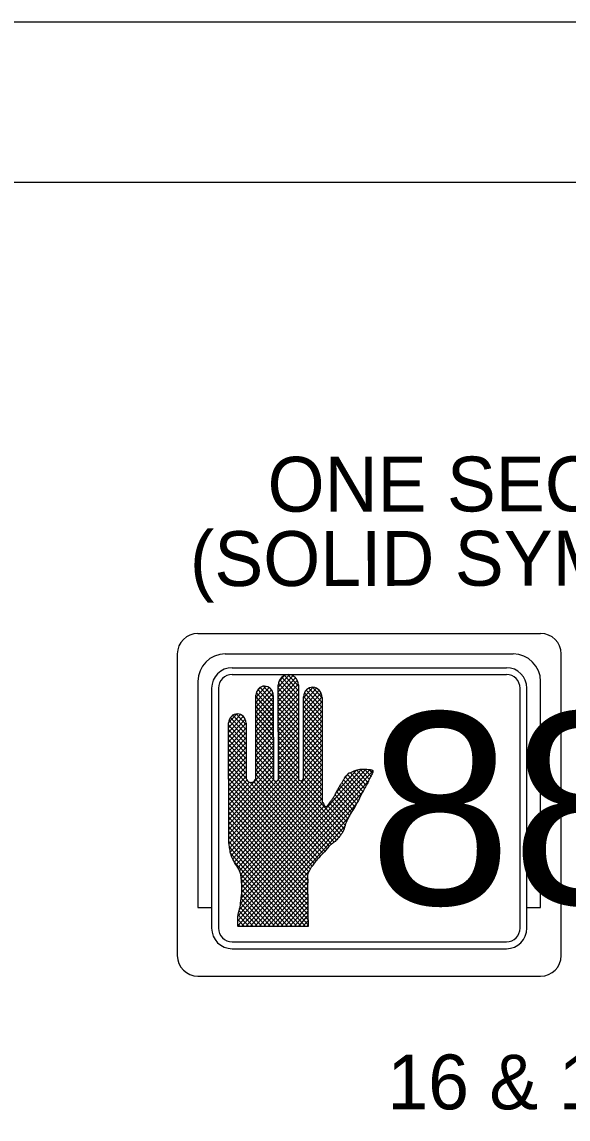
# Model space of a CAD drawing. Extents: x 1710114 to 1711114, y 557211 to 557851.
# Drawn here: x 1710492.9 to 1710532.7, y 557771.1 to 557851.1 of the extents above; entities that cross this region are included whole.
import ezdxf

# ---------------------------------------------------------------- set-up
doc = ezdxf.new("R2010")
doc.units = 0
for name, color, linetype in [('E_Existing ROW', 7, 'Continuous'), ('R_Alt Surface', 7, 'Continuous'), ('R_Alt Surface Annot', 7, 'Continuous'), ('R_Dimension', 7, 'Continuous')]:
    doc.layers.add(name, color=color, linetype=linetype)

msp = doc.modelspace()

# ---------------------------------------------------------------- linework, layer by layer
at = {"layer": 'E_Existing ROW'}
for p, q in [((1710505.726, 557806.546), (1710530.726, 557806.546)), ((1710504.226, 557805.046), (1710504.226, 557783.046)), ((1710507.726, 557805.046), (1710528.726, 557805.046)), ((1710532.226, 557783.046), (1710532.226, 557805.046)), ((1710508.226, 557804.046), (1710528.226, 557804.046)), ((1710505.726, 557803.046), (1710505.726, 557786.546)), ((1710508.226, 557803.546), (1710528.226, 557803.546)), ((1710511.59, 557802.63), (1710512.412, 557803.543)), ((1710511.59, 557802.277), (1710512.655, 557803.46)), ((1710511.591, 557801.924), (1710512.84, 557803.312)), ((1710511.591, 557801.571), (1710512.974, 557803.107)), ((1710511.592, 557801.218), (1710513.049, 557802.837)), ((1710511.605, 557802.905), (1710513.055, 557801.294)), ((1710511.644, 557803.043), (1710512.045, 557803.489)), ((1710511.696, 557803.158), (1710513.055, 557801.648)), ((1710511.841, 557803.35), (1710513.054, 557802.002)), ((1710512.037, 557803.486), (1710513.054, 557802.356)), ((1710512.298, 557803.549), (1710513.053, 557802.71)), ((1710512.765, 557803.384), (1710512.906, 557803.227)), ((1710513.053, 557802.792), (1710513.061, 557796.014)), ((1710530.726, 557786.546), (1710530.726, 557803.046)), ((1710506.726, 557802.546), (1710506.726, 557785.046)), ((1710507.226, 557802.546), (1710507.226, 557785.046)), ((1710509.952, 557801.871), (1710510.689, 557802.69)), ((1710509.952, 557801.518), (1710510.921, 557802.594)), ((1710509.958, 557796.073), (1710509.952, 557802.038)), ((1710509.953, 557801.164), (1710511.09, 557802.428)), ((1710509.953, 557800.811), (1710511.198, 557802.195)), ((1710509.987, 557802.228), (1710511.226, 557800.851)), ((1710510.009, 557802.288), (1710510.32, 557802.633)), ((1710510.104, 557802.452), (1710511.226, 557801.205)), ((1710510.279, 557802.61), (1710511.225, 557801.559)), ((1710510.521, 557802.695), (1710511.225, 557801.913)), ((1710510.946, 557802.576), (1710511.115, 557802.388)), ((1710511.224, 557802.024), (1710511.231, 557795.978)), ((1710511.597, 557795.946), (1710511.59, 557802.773)), ((1710511.59, 557802.568), (1710513.055, 557800.94)), ((1710511.59, 557802.214), (1710513.056, 557800.586)), ((1710511.592, 557800.865), (1710513.054, 557802.489)), ((1710511.592, 557800.512), (1710513.054, 557802.136)), ((1710513.42, 557801.835), (1710514.126, 557802.619)), ((1710513.421, 557801.482), (1710514.383, 557802.551)), ((1710513.421, 557801.129), (1710514.572, 557802.408)), ((1710513.421, 557800.776), (1710514.708, 557802.205)), ((1710513.497, 557802.217), (1710514.782, 557800.789)), ((1710513.635, 557802.417), (1710514.782, 557801.143)), ((1710513.827, 557802.557), (1710514.782, 557801.497)), ((1710514.089, 557802.62), (1710514.781, 557801.851)), ((1710529.226, 557785.046), (1710529.226, 557802.546)), ((1710529.726, 557785.046), (1710529.726, 557802.546)), ((1710509.952, 557801.914), (1710511.227, 557800.497)), ((1710509.952, 557801.56), (1710511.227, 557800.143)), ((1710509.953, 557800.458), (1710511.225, 557801.871)), ((1710509.953, 557801.206), (1710511.227, 557799.789)), ((1710509.954, 557800.105), (1710511.225, 557801.518)), ((1710511.591, 557801.86), (1710513.056, 557800.232)), ((1710511.591, 557801.506), (1710513.057, 557799.878)), ((1710511.593, 557800.158), (1710513.054, 557801.782)), ((1710511.593, 557799.805), (1710513.055, 557801.429)), ((1710513.427, 557795.981), (1710513.42, 557801.929)), ((1710513.421, 557801.595), (1710514.783, 557800.081)), ((1710513.421, 557801.241), (1710514.783, 557799.727)), ((1710513.422, 557801.947), (1710514.783, 557800.435)), ((1710513.422, 557800.423), (1710514.779, 557801.931)), ((1710513.422, 557800.07), (1710514.782, 557801.58)), ((1710513.423, 557799.717), (1710514.782, 557801.227)), ((1710514.781, 557801.882), (1710514.79, 557794.225)), ((1710507.964, 557800.015), (1710508.559, 557800.677)), ((1710507.964, 557799.662), (1710508.834, 557800.629)), ((1710507.964, 557799.309), (1710509.03, 557800.493)), ((1710508.11, 557800.424), (1710509.238, 557799.171)), ((1710508.284, 557800.585), (1710509.237, 557799.525)), ((1710508.523, 557800.673), (1710509.237, 557799.879)), ((1710508.926, 557800.579), (1710509.148, 557800.332)), ((1710509.953, 557800.852), (1710511.228, 557799.435)), ((1710509.953, 557800.498), (1710511.228, 557799.081)), ((1710509.954, 557799.752), (1710511.226, 557801.165)), ((1710509.955, 557799.399), (1710511.226, 557800.812)), ((1710509.955, 557799.046), (1710511.227, 557800.459)), ((1710511.592, 557801.152), (1710513.057, 557799.524)), ((1710511.592, 557800.798), (1710513.057, 557799.17)), ((1710511.592, 557800.444), (1710513.058, 557798.816)), ((1710511.594, 557799.452), (1710513.055, 557801.076)), ((1710511.594, 557799.099), (1710513.056, 557800.723)), ((1710513.421, 557800.887), (1710514.784, 557799.373)), ((1710513.422, 557800.533), (1710514.784, 557799.019)), ((1710513.423, 557799.364), (1710514.782, 557800.874)), ((1710513.423, 557799.011), (1710514.783, 557800.521)), ((1710507.973, 557791.775), (1710507.963, 557800.018)), ((1710507.964, 557799.88), (1710509.239, 557798.463)), ((1710507.965, 557798.956), (1710509.168, 557800.292)), ((1710507.965, 557798.603), (1710509.236, 557800.015)), ((1710507.966, 557798.249), (1710509.237, 557799.662)), ((1710507.996, 557800.198), (1710509.238, 557798.817)), ((1710509.237, 557800.003), (1710509.241, 557796.072)), ((1710509.954, 557800.144), (1710511.229, 557798.727)), ((1710509.954, 557799.79), (1710511.229, 557798.373)), ((1710509.955, 557798.693), (1710511.227, 557800.106)), ((1710509.956, 557798.34), (1710511.227, 557799.752)), ((1710511.593, 557800.09), (1710513.058, 557798.462)), ((1710511.593, 557799.736), (1710513.058, 557798.108)), ((1710511.594, 557798.746), (1710513.056, 557800.37)), ((1710511.595, 557798.393), (1710513.056, 557800.017)), ((1710511.595, 557798.04), (1710513.057, 557799.664)), ((1710513.422, 557800.179), (1710514.785, 557798.665)), ((1710513.423, 557799.825), (1710514.785, 557798.311)), ((1710513.424, 557798.657), (1710514.783, 557800.168)), ((1710513.424, 557798.304), (1710514.783, 557799.814)), ((1710507.964, 557799.526), (1710509.239, 557798.109)), ((1710507.965, 557799.172), (1710509.239, 557797.755)), ((1710507.965, 557798.818), (1710509.24, 557797.401)), ((1710507.966, 557797.896), (1710509.238, 557799.309)), ((1710507.966, 557797.543), (1710509.238, 557798.956)), ((1710509.955, 557799.436), (1710511.229, 557798.019)), ((1710509.955, 557799.082), (1710511.23, 557797.665)), ((1710509.956, 557797.986), (1710511.228, 557799.399)), ((1710509.957, 557797.633), (1710511.228, 557799.046)), ((1710511.594, 557799.382), (1710513.059, 557797.754)), ((1710511.594, 557799.028), (1710513.059, 557797.4)), ((1710511.596, 557797.687), (1710513.057, 557799.311)), ((1710511.596, 557797.334), (1710513.058, 557798.958)), ((1710513.423, 557799.471), (1710514.785, 557797.957)), ((1710513.423, 557799.117), (1710514.786, 557797.603)), ((1710513.425, 557797.951), (1710514.784, 557799.461)), ((1710513.425, 557797.598), (1710514.784, 557799.108)), ((1710507.965, 557798.464), (1710509.24, 557797.047)), ((1710507.966, 557798.11), (1710509.241, 557796.693)), ((1710507.967, 557797.19), (1710509.238, 557798.603)), ((1710507.967, 557796.837), (1710509.239, 557798.25)), ((1710509.955, 557798.728), (1710511.23, 557797.311)), ((1710509.956, 557798.374), (1710511.231, 557796.957)), ((1710509.956, 557798.02), (1710511.231, 557796.603)), ((1710509.957, 557797.28), (1710511.229, 557798.693)), ((1710509.957, 557796.927), (1710511.229, 557798.34)), ((1710509.958, 557796.574), (1710511.229, 557797.987)), ((1710511.594, 557798.674), (1710513.06, 557797.046)), ((1710511.595, 557798.32), (1710513.06, 557796.692)), ((1710511.596, 557796.98), (1710513.058, 557798.604)), ((1710511.597, 557796.627), (1710513.058, 557798.251)), ((1710513.424, 557798.763), (1710514.786, 557797.249)), ((1710513.424, 557798.409), (1710514.786, 557796.895)), ((1710513.425, 557797.245), (1710514.784, 557798.755)), ((1710513.425, 557798.055), (1710514.787, 557796.541)), ((1710513.426, 557796.892), (1710514.785, 557798.402)), ((1710513.426, 557796.539), (1710514.785, 557798.049)), ((1710507.966, 557797.756), (1710509.241, 557796.339)), ((1710507.966, 557797.402), (1710509.253, 557795.973)), ((1710507.967, 557796.484), (1710509.239, 557797.897)), ((1710507.968, 557796.131), (1710509.24, 557797.544)), ((1710507.968, 557795.778), (1710509.24, 557797.191)), ((1710507.97, 557793.659), (1710511.23, 557797.281)), ((1710507.985, 557791.553), (1710513.06, 557797.192)), ((1710508.265, 557790.097), (1710514.786, 557797.342)), ((1710509.957, 557797.666), (1710511.231, 557796.249)), ((1710509.957, 557797.312), (1710511.247, 557795.878)), ((1710509.958, 557796.221), (1710511.23, 557797.634)), ((1710511.594, 557795.917), (1710513.059, 557797.545)), ((1710511.595, 557797.966), (1710513.06, 557796.338)), ((1710511.596, 557797.612), (1710513.055, 557795.99)), ((1710511.596, 557797.258), (1710516.29, 557792.043)), ((1710511.597, 557796.274), (1710513.059, 557797.898)), ((1710513.425, 557797.701), (1710514.787, 557796.187)), ((1710513.425, 557797.347), (1710514.787, 557795.834)), ((1710513.427, 557796.186), (1710514.785, 557797.695)), ((1710507.967, 557797.048), (1710514.344, 557789.962)), ((1710507.967, 557796.694), (1710514.197, 557789.772)), ((1710507.969, 557795.424), (1710509.24, 557796.838)), ((1710507.969, 557795.071), (1710509.241, 557796.484)), ((1710507.971, 557793.306), (1710511.231, 557796.928)), ((1710507.971, 557792.953), (1710511.231, 557796.574)), ((1710507.996, 557791.212), (1710513.06, 557796.839)), ((1710508.045, 557790.913), (1710513.06, 557796.486)), ((1710508.389, 557789.881), (1710514.786, 557796.989)), ((1710508.514, 557789.666), (1710514.787, 557796.636)), ((1710508.648, 557785.573), (1710518.495, 557796.513)), ((1710508.659, 557785.938), (1710518.264, 557796.611)), ((1710508.764, 557786.408), (1710517.975, 557796.643)), ((1710508.834, 557786.84), (1710517.657, 557796.643)), ((1710509.957, 557796.958), (1710515.304, 557791.017)), ((1710509.958, 557796.604), (1710515.147, 557790.838)), ((1710511.596, 557796.904), (1710516.15, 557791.844)), ((1710511.597, 557796.55), (1710516, 557791.657)), ((1710513.426, 557796.993), (1710514.788, 557795.48)), ((1710513.426, 557796.639), (1710514.788, 557795.126)), ((1710515.828, 557794.965), (1710517.283, 557796.582)), ((1710516.832, 557796.39), (1710517.874, 557795.233)), ((1710517.057, 557796.494), (1710518.002, 557795.444)), ((1710517.292, 557796.586), (1710518.124, 557795.662)), ((1710517.559, 557796.643), (1710518.225, 557795.903)), ((1710517.877, 557796.643), (1710518.338, 557796.131)), ((1710518.219, 557796.617), (1710518.449, 557796.361)), ((1710507.968, 557796.34), (1710514.063, 557789.568)), ((1710507.968, 557795.986), (1710513.919, 557789.374)), ((1710507.968, 557795.632), (1710513.807, 557789.144)), ((1710507.969, 557794.718), (1710509.241, 557796.131)), ((1710507.97, 557794.365), (1710509.304, 557795.848)), ((1710507.97, 557794.012), (1710509.485, 557795.696)), ((1710507.972, 557792.599), (1710511.231, 557796.221)), ((1710507.972, 557792.246), (1710511.245, 557795.883)), ((1710507.972, 557791.893), (1710511.455, 557795.763)), ((1710508.094, 557790.614), (1710513.061, 557796.133)), ((1710508.158, 557790.332), (1710513.119, 557795.843)), ((1710508.638, 557789.45), (1710514.787, 557796.283)), ((1710508.649, 557785.22), (1710518.188, 557795.819)), ((1710508.759, 557789.231), (1710514.787, 557795.93)), ((1710508.853, 557788.982), (1710514.788, 557795.577)), ((1710509.509, 557795.688), (1710514.504, 557790.138)), ((1710509.787, 557795.733), (1710514.666, 557790.312)), ((1710509.933, 557795.925), (1710514.829, 557790.484)), ((1710509.958, 557796.25), (1710514.991, 557790.658)), ((1710511.339, 557795.776), (1710515.475, 557791.18)), ((1710511.577, 557795.866), (1710515.663, 557791.325)), ((1710511.597, 557796.196), (1710515.844, 557791.478)), ((1710513.234, 557795.792), (1710516.384, 557792.292)), ((1710513.42, 557795.939), (1710514.789, 557794.418)), ((1710513.427, 557796.285), (1710514.788, 557794.772)), ((1710516.232, 557795.643), (1710517.41, 557794.334)), ((1710516.353, 557795.862), (1710517.527, 557794.557)), ((1710516.429, 557795.986), (1710516.771, 557796.366)), ((1710516.484, 557796.069), (1710517.639, 557794.786)), ((1710516.635, 557796.255), (1710517.751, 557795.015)), ((1710507.969, 557795.278), (1710513.723, 557788.884)), ((1710507.969, 557794.924), (1710513.734, 557788.518)), ((1710508.888, 557788.668), (1710514.788, 557795.223)), ((1710508.914, 557785.161), (1710517.712, 557794.937)), ((1710508.919, 557788.349), (1710514.788, 557794.87)), ((1710515.743, 557794.772), (1710516.908, 557793.477)), ((1710515.848, 557795.008), (1710517.039, 557793.685)), ((1710515.969, 557795.228), (1710517.169, 557793.895)), ((1710516.093, 557795.444), (1710517.291, 557794.113)), ((1710507.969, 557794.57), (1710513.72, 557788.18)), ((1710507.97, 557794.216), (1710513.721, 557787.826)), ((1710508.879, 557787.244), (1710514.951, 557793.991)), ((1710508.935, 557787.66), (1710514.835, 557794.214)), ((1710508.938, 557788.016), (1710514.789, 557794.517)), ((1710509.232, 557785.161), (1710517.294, 557794.118)), ((1710515.173, 557793.99), (1710516.465, 557792.555)), ((1710515.322, 557794.179), (1710516.56, 557792.803)), ((1710515.47, 557794.368), (1710516.668, 557793.037)), ((1710515.604, 557794.573), (1710516.786, 557793.259)), ((1710507.97, 557793.862), (1710513.737, 557787.455)), ((1710507.971, 557793.508), (1710513.739, 557787.099)), ((1710507.971, 557793.154), (1710513.739, 557786.745)), ((1710507.971, 557792.8), (1710513.74, 557786.391)), ((1710507.972, 557792.446), (1710513.742, 557786.035)), ((1710509.551, 557785.162), (1710516.711, 557793.118)), ((1710509.87, 557785.162), (1710516.428, 557792.45)), ((1710507.972, 557792.092), (1710513.756, 557785.666)), ((1710507.975, 557791.736), (1710513.776, 557785.29)), ((1710507.987, 557791.369), (1710513.568, 557785.167)), ((1710508.037, 557790.96), (1710513.25, 557785.167)), ((1710508.109, 557790.526), (1710512.933, 557785.166)), ((1710508.42, 557789.827), (1710512.615, 557785.166)), ((1710510.188, 557785.163), (1710513.861, 557789.244)), ((1710508.851, 557788.995), (1710512.297, 557785.166)), ((1710508.897, 557788.59), (1710511.979, 557785.165)), ((1710510.507, 557785.163), (1710513.73, 557788.745)), ((1710510.825, 557785.164), (1710513.728, 557788.389)), ((1710508.929, 557788.201), (1710511.661, 557785.165)), ((1710508.941, 557787.834), (1710511.344, 557785.164)), ((1710511.144, 557785.164), (1710513.719, 557788.025)), ((1710511.462, 557785.164), (1710513.727, 557787.68)), ((1710508.839, 557786.887), (1710510.39, 557785.163)), ((1710508.873, 557787.202), (1710510.708, 557785.163)), ((1710508.92, 557787.504), (1710511.026, 557785.164)), ((1710511.781, 557785.165), (1710513.738, 557787.34)), ((1710512.1, 557785.165), (1710513.739, 557786.987)), ((1710505.726, 557786.546), (1710506.726, 557786.546)), ((1710508.664, 557786.02), (1710509.437, 557785.162)), ((1710508.729, 557786.302), (1710509.755, 557785.162)), ((1710508.803, 557786.573), (1710510.072, 557785.162)), ((1710512.418, 557785.166), (1710513.739, 557786.633)), ((1710512.737, 557785.166), (1710513.74, 557786.28)), ((1710529.726, 557786.546), (1710530.726, 557786.546)), ((1710508.649, 557785.33), (1710508.801, 557785.161)), ((1710508.674, 557785.161), (1710508.649, 557785.192)), ((1710508.65, 557785.683), (1710509.119, 557785.161)), ((1710513.055, 557785.167), (1710513.745, 557785.933)), ((1710513.374, 557785.167), (1710513.759, 557785.595)), ((1710513.693, 557785.168), (1710513.776, 557785.26)), ((1710513.753, 557785.168), (1710508.674, 557785.161)), ((1710513.777, 557785.162), (1710513.753, 557785.168)), ((1710508.226, 557784.046), (1710528.226, 557784.046)), ((1710508.226, 557783.546), (1710528.226, 557783.546)), ((1710505.726, 557781.546), (1710530.726, 557781.546))]:
    msp.add_line(p, q, dxfattribs=at)
for centre, radius, start, end in [((1710505.726, 557805.046), 1.5, 90, 180), ((1710530.726, 557805.046), 1.5, 0, 90), ((1710507.726, 557803.046), 2, 90, 180), ((1710528.726, 557803.046), 2, 0, 90), ((1710508.226, 557802.546), 1.5, 90, 180), ((1710528.226, 557802.546), 1.5, 0, 90), ((1710508.226, 557802.546), 1, 90, 180), ((1710528.226, 557802.546), 1, 0, 90), ((1710508.226, 557785.046), 1.5, 180, 270), ((1710508.226, 557785.046), 1, 180, 270), ((1710528.226, 557785.046), 1.5, 270, 0), ((1710528.226, 557785.046), 1, 270, 0), ((1710505.726, 557783.046), 1.5, 180, 270), ((1710530.726, 557783.046), 1.5, 270, 0)]:
    msp.add_arc(centre, radius, start, end, dxfattribs=at)
for centre, major_axis, start_param, end_param in [((1710512.322, 557802.735), (0, -0.814), 1.640121, 4.665593), ((1710510.588, 557801.99), (0, -0.709), 1.618611, 4.644084), ((1710514.099, 557801.862), (0, -0.758), 1.597842, 4.623315), ((1710508.6, 557799.97), (0, -0.709), 1.618611, 4.644084), ((1710509.6, 557796.073), (0, -0.398), 4.713646, 7.855239), ((1710511.415, 557795.962), (0, -0.204), 4.633755, 7.775348), ((1710513.241, 557795.999), (0, -0.207), 4.624552, 7.766145)]:
    msp.add_ellipse(centre, major_axis=major_axis, ratio=0.9, start_param=start_param, end_param=end_param, dxfattribs=at)
for points in [[(1710514.789, 557794.226), (1710514.84, 557794.212), (1710514.91, 557794.057), (1710514.998, 557793.938), (1710515.05, 557793.919), (1710515.138, 557793.939), (1710515.192, 557794.019), (1710515.35, 557794.213), (1710515.473, 557794.371), (1710515.543, 557794.487), (1710515.613, 557794.585), (1710515.736, 557794.761), (1710515.806, 557794.918), (1710515.911, 557795.133), (1710515.982, 557795.251), (1710516.105, 557795.465), (1710516.245, 557795.662), (1710516.351, 557795.857), (1710516.473, 557796.052), (1710516.58, 557796.19), (1710516.736, 557796.347), (1710516.929, 557796.426), (1710517.036, 557796.485), (1710517.194, 557796.542), (1710517.334, 557796.603), (1710517.547, 557796.643), (1710517.722, 557796.643), (1710517.951, 557796.643), (1710518.162, 557796.624), (1710518.408, 557796.585), (1710518.478, 557796.544), (1710518.494, 557796.487), (1710518.391, 557796.233), (1710518.32, 557796.095), (1710518.251, 557795.957), (1710518.18, 557795.802), (1710518.144, 557795.704), (1710518.004, 557795.449), (1710517.795, 557795.097), (1710517.513, 557794.53), (1710517.162, 557793.882), (1710516.882, 557793.432), (1710516.723, 557793.139), (1710516.583, 557792.864), (1710516.501, 557792.646), (1710516.458, 557792.535), (1710516.301, 557792.063), (1710516.056, 557791.73), (1710515.862, 557791.496), (1710515.582, 557791.259), (1710515.405, 557791.122), (1710514.949, 557790.612), (1710514.545, 557790.183), (1710514.282, 557789.888), (1710514.053, 557789.554), (1710513.939, 557789.409), (1710513.843, 557789.204), (1710513.737, 557789.007), (1710513.737, 557788.577), (1710513.72, 557788.191), (1710513.721, 557787.837), (1710513.738, 557787.369), (1710513.739, 557786.919), (1710513.74, 557786.195), (1710513.758, 557785.612), (1710513.776, 557785.396), (1710513.776, 557785.238), (1710513.776, 557785.163)], [(1710508.649, 557785.192), (1710508.648, 557785.506), (1710508.665, 557786.034), (1710508.805, 557786.582), (1710508.874, 557787.208), (1710508.927, 557787.56), (1710508.926, 557788.245), (1710508.872, 557788.812), (1710508.819, 557789.105), (1710508.555, 557789.593), (1710508.273, 557790.083), (1710508.114, 557790.494), (1710508.043, 557790.924), (1710507.989, 557791.257), (1710507.989, 557791.471), (1710507.973, 557791.775)]]:
    msp.add_spline(points, degree=3, dxfattribs=at)
at = {"layer": 'R_Alt Surface'}
msp.add_line((1710151.54, 557839.465), (1711100.08, 557839.465), dxfattribs=at)
at = {"layer": 'R_Alt Surface Annot'}
msp.add_line((1710114.338, 557851.149), (1711114.338, 557851.149), dxfattribs=at)
msp.add_lwpolyline([(1710114.318, 557851.149), (1711114.338, 557851.149), (1711114.338, 557211.137), (1710114.318, 557211.137)], close=True, dxfattribs=at)

# ---------------------------------------------------------------- texts
at = {"layer": 'E_Existing ROW'}
for s, height, p in [('ONE SECTION', 4, (1710510.812, 557815.424)), ('(SOLID SYMBOL)', 4, (1710505.146, 557809.998)), ('88', 14, (1710518.19, 557786.767))]:
    msp.add_text(s, height=height, rotation=0.07203, dxfattribs=at).set_placement(p)
at = {"layer": 'R_Dimension'}
msp.add_text('16 & 17', height=4, dxfattribs=at).set_placement((1710519.548, 557771.829))

doc.saveas('drawing.dxf')
